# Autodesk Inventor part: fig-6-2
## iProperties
Created: 2004-05
Part Number: fig-6-2
Document SubType Name: Modeling
Designer: CADCIM Technologies
Manufacturer: Standard
Standards Organization: Custom
Density: 1 g/cm^3
Author: CADCIM Technologies
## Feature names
1. Extrusion1
2. Hole1
3. Circular Pattern1
